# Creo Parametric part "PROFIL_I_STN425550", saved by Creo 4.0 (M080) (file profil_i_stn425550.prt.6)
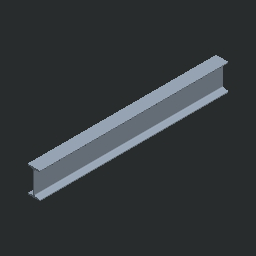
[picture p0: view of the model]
Units: millimeter Kilogram Sec (mmKs); MM, KILOGRAM, SECS
Materials in the file: OCEL_N

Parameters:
  MFG_WP_MATERIAL = "OCEL"
  NAZOV = "PROFIL_I_STN425550"
  NORMA = "STN 42 5550"
  PTC_MATERIAL_NAME = "OCEL_N"

Other parameters: HMOTNOST, HUSTOTA, D9, D7, D10

Created from: I.PRT

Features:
  1. datum plane "DTM1"
  2. datum plane "DTM2"
  3. datum plane "DTM3"

Named dimensions: b_ctvrt

Layers: 1, 2, 3, 4, 5, 6, 7, 8, 9, 10, 11, 12, 13, 14, 15, 16, 17, 18, 19, 20, 21, 22, 23, 24, 25, 26, 27, 28, 29, 30, 31, 32

Family table entries: GENERIC, PROFIL_I_140, PROFIL_I_STN425550, value(d_val), value(i_val), PROFIL_I_160, PROFIL_I_STN425550, 2/d, 2/#, PROFIL_I_180, PROFIL_I_STN425550, PROFIL_I_200, PROFIL_I_STN425550, 2/i, PROFIL_I_220, PROFIL_I_STN425550, PROFIL_I_240, PROFIL_I_STN425550, 2/n, PROFIL_I_260, PROFIL_I_STN425550, PROFIL_I_300, PROFIL_I_STN425550, PROFIL_I_320, PROFIL_I_STN425550, 2/t, 2/', 2/', PROFIL_I_360, PROFIL_I_STN425550, 2/*, 2/*, PROFIL_I_400, PROFIL_I_STN425550, 2/y, # Pro/TABLE, [] S 92;, [] W 10;, [A] W  3;, [B] W 13;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

Surfaces: 14 plane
